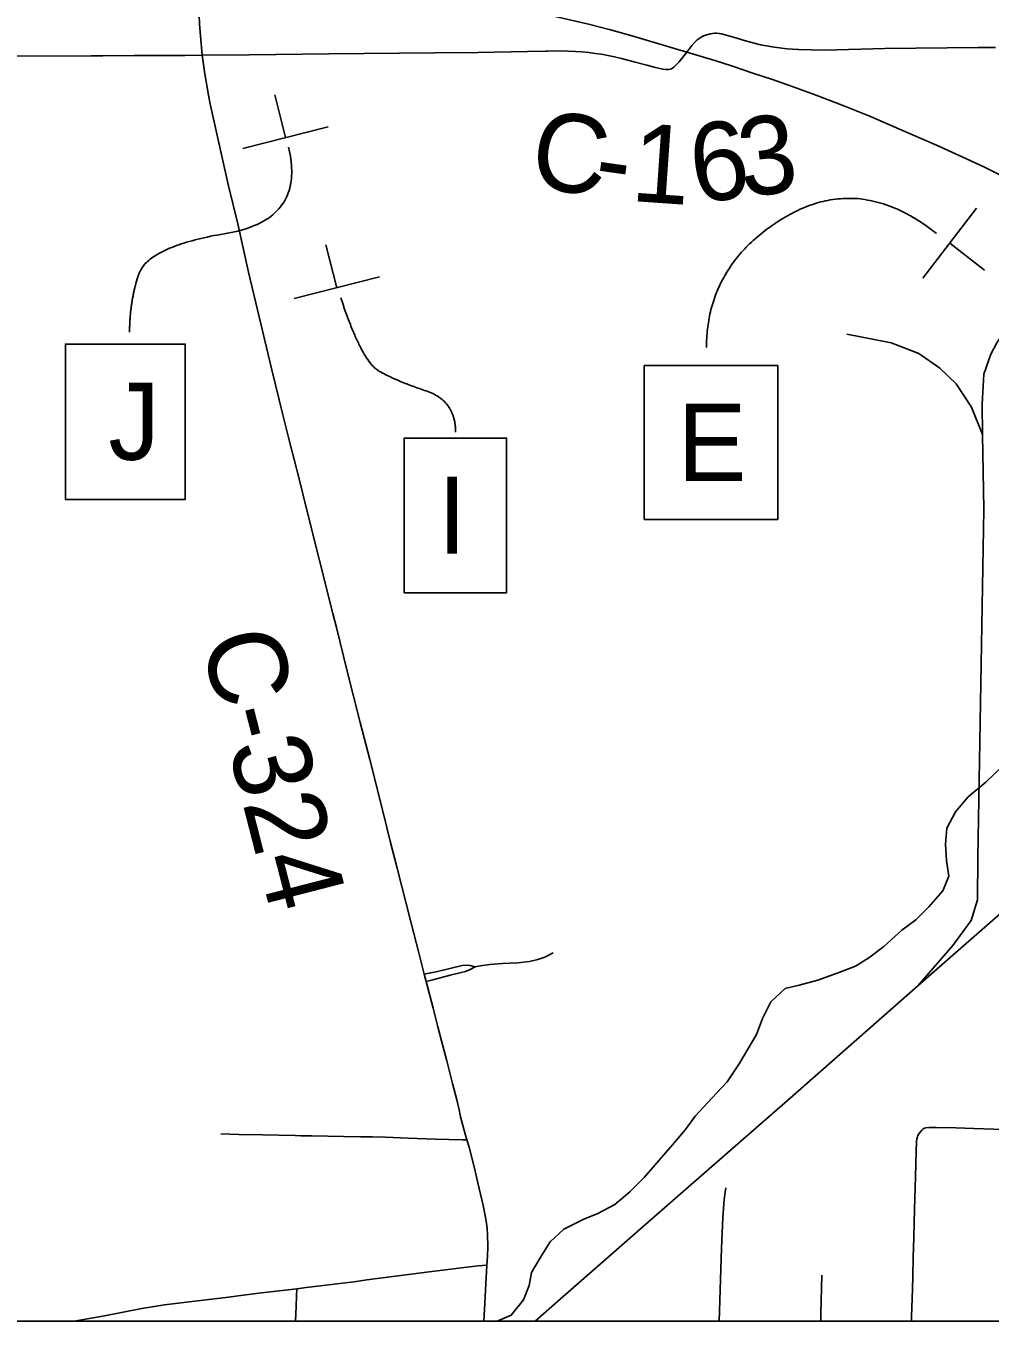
# Model space of a CAD drawing. Extents: x 0 to 34, y 0 to 22.
# Drawn here: x 2.507 to 4.256, y 4.299 to 6.648 of the extents above; entities that cross this region are included whole.
import ezdxf

# ---------------------------------------------------------------- set-up
doc = ezdxf.new("R2010")
doc.units = 0
for name, color, linetype in [('GM_X_City_Street', 7, 'Continuous'), ('GM_X_County_Road', 7, 'Continuous'), ('GM_X_County_Road_Text', 7, 'Continuous'), ('GM_X_Minor_River', 7, 'Continuous'), ('GM_X_Rail_Line', 7, 'Continuous'), ('GM_X_State_Route', 7, 'Continuous'), ('SH_Text', 7, 'Continuous'), ('SN_P_Signs', 7, 'Continuous')]:
    doc.layers.add(name, color=color, linetype=linetype)

msp = doc.modelspace()

# ---------------------------------------------------------------- linework, layer by layer
at = {"layer": 'GM_X_City_Street'}
for points in [[(3.3225, 4.9419), (3.3316, 4.9436), (3.3486, 4.9462), (3.372, 4.9477), (3.3997, 4.9489), (3.421, 4.9516), (3.4358, 4.9549), (3.4487, 4.9594), (3.4637, 4.9668)], [(3.23, 4.9285), (3.2416, 4.9309), (3.2516, 4.9329), (3.2988, 4.9439), (3.308, 4.9449), (3.3131, 4.9441), (3.3225, 4.9419)], [(3.2334, 4.915), (3.2454, 4.9181), (3.277, 4.9263), (3.2942, 4.9306), (3.3046, 4.9334), (3.3119, 4.936), (3.3225, 4.9419)], [(2.8607, 4.6385), (2.8933, 4.6376), (2.9366, 4.6369), (2.9954, 4.6356), (3.0061, 4.6354), (3.0261, 4.6352), (3.0833, 4.6342), (3.1146, 4.6336), (3.1361, 4.6334), (3.1597, 4.6325), (3.2008, 4.631), (3.25, 4.629), (3.2744, 4.6282), (3.2995, 4.6277), (3.3073, 4.6276)], [(4.1138, 4.2991), (4.1139, 4.3067), (4.1155, 4.3568), (4.1161, 4.3808), (4.1166, 4.4146), (4.1179, 4.4512), (4.1195, 4.5017), (4.1208, 4.5615), (4.1221, 4.6069), (4.1232, 4.6257), (4.1237, 4.6296), (4.1245, 4.6333), (4.1255, 4.6358), (4.127, 4.6386), (4.1294, 4.6415), (4.1323, 4.6454)], [(4.1323, 4.6454), (4.135, 4.6477), (4.1376, 4.649), (4.1399, 4.6497), (4.1461, 4.6502), (4.1588, 4.6505), (4.1942, 4.6495), (4.2271, 4.6484), (4.2811, 4.6466), (4.2887, 4.6464), (4.3195, 4.6457), (4.3751, 4.6449), (4.4061, 4.6443), (4.4384, 4.6435), (4.4562, 4.6432), (4.5023, 4.6422), (4.5604, 4.6401), (4.621, 4.6386), (4.6306, 4.6382)], [(3.765, 4.2991), (3.7692, 4.4316), (3.7718, 4.4871), (3.774, 4.5195), (3.7758, 4.5332), (3.7772, 4.5406)], [(2.5939, 4.2991), (2.6053, 4.301), (2.6498, 4.3088), (2.7175, 4.3219), (2.7589, 4.3287), (2.7984, 4.3333), (2.8749, 4.3426), (2.9012, 4.3459), (2.921, 4.3483), (2.9348, 4.3501), (2.9829, 4.3559), (2.9989, 4.3578), (3.0158, 4.3599), (3.0414, 4.3631), (3.0712, 4.3667), (3.1026, 4.3705), (3.1259, 4.3738), (3.1775, 4.3806), (3.2439, 4.3893), (3.2687, 4.3923), (3.2975, 4.3957), (3.3274, 4.3991), (3.3433, 4.4005)], [(3.9493, 4.2991), (3.9496, 4.312), (3.9512, 4.3824)], [(2.9963, 4.2991), (2.9975, 4.326), (2.9983, 4.3441), (2.9989, 4.3578)]]:
    msp.add_lwpolyline(points, dxfattribs=at)
at = {"layer": 'GM_X_County_Road'}
for p, q in [((2.6466, 6.5943), (2.7037, 6.5945)), ((3.0151, 5.7772), (3.0033, 5.8242)), ((3.0638, 5.5828), (3.0151, 5.7772))]:
    msp.add_line(p, q, dxfattribs=at)
for points in [[(2.827, 6.5951), (2.8224, 6.6514), (2.8208, 6.6847)], [(3.7061, 6.601), (3.7154, 6.6129), (3.7201, 6.6183), (3.7251, 6.6232), (3.7305, 6.627), (3.7364, 6.6302), (3.7428, 6.6325), (3.7483, 6.634), (3.7531, 6.6349), (3.7564, 6.6353), (3.7601, 6.6354), (3.765, 6.6349), (3.7694, 6.6339), (3.7911, 6.6278), (3.8127, 6.6214), (3.8401, 6.6142), (3.8645, 6.6099), (3.8885, 6.607), (3.9074, 6.6058)], [(2.827, 6.5951), (2.9122, 6.596), (3.0568, 6.598), (3.2489, 6.5994), (3.3278, 6.6), (3.4173, 6.6018), (3.4504, 6.6023)], [(3.4504, 6.6023), (3.4528, 6.6024), (3.4736, 6.6029), (3.4904, 6.6027), (3.5045, 6.6021), (3.5156, 6.6013), (3.5286, 6.6002), (3.5402, 6.5986), (3.5513, 6.5969), (3.563, 6.5949), (3.5749, 6.5924), (3.5878, 6.5894), (3.6126, 6.5826), (3.6337, 6.5769), (3.6467, 6.5734), (3.6574, 6.5709), (3.6633, 6.5699), (3.6683, 6.5693), (3.6709, 6.5692), (3.6733, 6.5693), (3.6761, 6.5699), (3.6786, 6.5708), (3.6809, 6.5721), (3.6828, 6.5734), (3.6872, 6.5776), (3.6925, 6.5835), (3.7061, 6.601)], [(3.9074, 6.6058), (3.9097, 6.6056), (3.9324, 6.6051), (3.9561, 6.6047), (4.0655, 6.6077), (4.2347, 6.6093), (4.2664, 6.6095)], [(2.1588, 6.5903), (2.1951, 6.5904), (2.3095, 6.5919), (2.4337, 6.5934), (2.6257, 6.5942), (2.6466, 6.5943)], [(2.7037, 6.5945), (2.721, 6.5946), (2.7956, 6.5948), (2.827, 6.5951)], [(2.8417, 6.5065), (2.8382, 6.5228), (2.8317, 6.5613), (2.827, 6.5951)], [(3.0033, 5.8242), (2.9845, 5.8994), (2.9733, 5.9431), (2.9532, 6.0246), (2.9113, 6.2016), (2.8916, 6.2895), (2.8743, 6.3605), (2.8422, 6.5042), (2.8417, 6.5065)], [(3.1137, 5.3851), (3.0902, 5.4781), (3.0705, 5.5569), (3.0638, 5.5828)], [(3.1683, 5.1698), (3.156, 5.2191), (3.1312, 5.3178), (3.1137, 5.3851)], [(3.2054, 5.0232), (3.1806, 5.1204), (3.1683, 5.1698)], [(3.2334, 4.915), (3.23, 4.9285), (3.22, 4.9673), (3.2054, 5.0232)], [(3.2548, 4.8328), (3.2458, 4.867), (3.2334, 4.915)], [(3.2707, 4.7709), (3.2612, 4.8073), (3.2548, 4.8328)], [(3.2887, 4.7006), (3.2811, 4.7302), (3.2707, 4.7709)], [(3.3073, 4.6276), (3.3017, 4.6474), (3.2959, 4.6699), (3.293, 4.6826), (3.2887, 4.7006)], [(3.3433, 4.4005), (3.3446, 4.416), (3.3451, 4.4342), (3.3449, 4.4553), (3.344, 4.4678), (3.3424, 4.4806), (3.3394, 4.4969), (3.3367, 4.509), (3.327, 4.5497), (3.3203, 4.5791), (3.3112, 4.6143), (3.3073, 4.6276)], [(3.3381, 4.2991), (3.3391, 4.32), (3.3408, 4.3555), (3.3433, 4.4005)]]:
    msp.add_lwpolyline(points, dxfattribs=at)
at = {"layer": 'GM_X_Minor_River'}
msp.add_lwpolyline([(3.3613, 4.2991), (3.3622, 4.2992), (3.3876, 4.3099), (3.41, 4.3377), (3.4201, 4.3635), (3.4246, 4.3873), (3.4404, 4.414), (3.4581, 4.4427), (3.4834, 4.4658), (3.5191, 4.4842), (3.5446, 4.494), (3.5757, 4.5105), (3.6029, 4.5336), (3.6291, 4.5596), (3.6562, 4.5912), (3.6805, 4.619), (3.7039, 4.6468), (3.7216, 4.6708), (3.7515, 4.7034), (3.7796, 4.7331), (3.801, 4.7657), (3.8326, 4.8192), (3.8436, 4.8478), (3.8584, 4.8784), (3.8847, 4.9024), (3.9102, 4.9084), (3.9442, 4.9173), (3.9791, 4.9301), (4.0121, 4.9428), (4.0365, 4.9583), (4.0637, 4.9785), (4.0965, 5.0083), (4.1219, 5.0267), (4.1453, 5.0507), (4.1705, 5.0794), (4.1816, 5.1061), (4.1775, 5.1346), (4.1753, 5.164), (4.1778, 5.1934), (4.1935, 5.223), (4.2169, 5.2499), (4.2488, 5.2768), (4.2778, 5.3047)], dxfattribs=at)
at = {"layer": 'GM_X_Rail_Line'}
for points in [[(4.2429, 5.9073), (4.2421, 5.962), (4.2451, 6.0167), (4.2576, 6.053), (4.2685, 6.0735), (4.2921, 6.109)], [(4.2429, 5.9073), (4.2227, 5.9571), (4.1951, 5.9993), (4.165, 6.0276), (4.1274, 6.0539), (4.0769, 6.0736), (3.9967, 6.0891)], [(4.1252, 4.9071), (4.1889, 4.9801), (4.2218, 5.026), (4.2333, 5.0632), (4.2341, 5.1401), (4.2448, 5.7712), (4.2429, 5.9073)], [(3.4309, 4.2991), (3.4764, 4.3387), (3.6805, 4.5174), (3.8887, 4.6992), (4.1252, 4.9071), (4.1549, 4.9332), (4.3767, 5.1271), (4.5491, 5.2778), (4.631, 5.3498)]]:
    msp.add_lwpolyline(points, dxfattribs=at)
at = {"layer": 'GM_X_State_Route'}
for points in [[(2.8178, 6.755), (2.8925, 6.7505), (2.9497, 6.7461), (3.0027, 6.741), (3.0574, 6.7348), (3.0939, 6.7305), (3.1331, 6.7259), (3.1841, 6.719), (3.2394, 6.7103), (3.2992, 6.6996), (3.3531, 6.6894), (3.3985, 6.6803), (3.4461, 6.6701), (3.4886, 6.6606), (3.5279, 6.6513), (3.5678, 6.6414), (3.6046, 6.6313), (3.7061, 6.601)], [(3.7061, 6.601), (3.7571, 6.5856), (3.789, 6.5753), (3.826, 6.5629), (3.8615, 6.5511), (3.8991, 6.5378), (3.9389, 6.5233), (3.9911, 6.5035), (4.0396, 6.484), (4.092, 6.4614), (4.1589, 6.4322), (4.207, 6.4103), (4.245, 6.3925), (4.3023, 6.3646), (4.3522, 6.3392), (4.396, 6.3156), (4.4624, 6.2784), (4.5103, 6.2504), (4.5571, 6.2217), (4.6188, 6.1826), (4.6879, 6.1377), (4.7092, 6.1238)]]:
    msp.add_lwpolyline(points, dxfattribs=at)
at = {"layer": 'SH_Text'}
for points in [[(1.6712, 21.2991), (18.6712, 21.2991), (18.6712, 4.2991), (1.6712, 4.2991)], [(2.579, 5.7894), (2.7964, 5.7894), (2.7964, 6.0713), (2.579, 6.0713)], [(3.6289, 5.7529), (3.8711, 5.7529), (3.8711, 6.0323), (3.6289, 6.0323)], [(3.1935, 5.6202), (3.3792, 5.6202), (3.3792, 5.9009), (3.1935, 5.9009)]]:
    msp.add_lwpolyline(points, close=True, dxfattribs=at)
for points in [[(2.9838, 6.4287), (3.0152, 6.2964), (2.7294, 6.2483), (2.6953, 6.1495), (2.6953, 6.0926)], [(3.7419, 6.0649), (3.7419, 6.2144), (4.0189, 6.3838), (4.1592, 6.2718)], [(3.0784, 6.1552), (3.1164, 6.0402), (3.1792, 6.0044), (3.2868, 5.9685), (3.2868, 5.9115)]]:
    msp.add_open_spline(points, degree=2, dxfattribs=at)
at = {"layer": 'SN_P_Signs'}
for p, q in [((2.9782, 6.4458), (2.9586, 6.5234)), ((3.0558, 6.4654), (2.9006, 6.4263)), ((4.1342, 6.191), (4.2319, 6.3177)), ((3.0712, 6.1734), (3.0516, 6.251)), ((4.1831, 6.2544), (4.2464, 6.2055)), ((3.1487, 6.193), (2.9936, 6.1538))]:
    msp.add_line(p, q, dxfattribs=at)

# ---------------------------------------------------------------- texts
at = {"layer": 'GM_X_County_Road_Text'}
for s, height, rotation, p in [('C', 0.142, 351.5862, (3.4177, 6.3576)), ('3', 0.142, 6.8281, (3.8077, 6.3375)), ('1', 0.142, 356.0186, (3.6028, 6.331)), ('6', 0.142, 7.6538, (3.7215, 6.3259)), ('-', 0.142, 351.8008, (3.5337, 6.3405)), ('C-324', 0.14205, 284.4392, (2.8236, 5.5357))]:
    msp.add_text(s, height=height, rotation=rotation, dxfattribs=at).set_placement(p)
at = {"layer": 'SH_Text'}
for s, p in [('J', (2.6567, 5.8613)), ('E', (3.6894, 5.8229)), ('I', (3.2546, 5.6909))]:
    msp.add_text(s, height=0.14, dxfattribs=at).set_placement(p)

doc.saveas('drawing.dxf')
